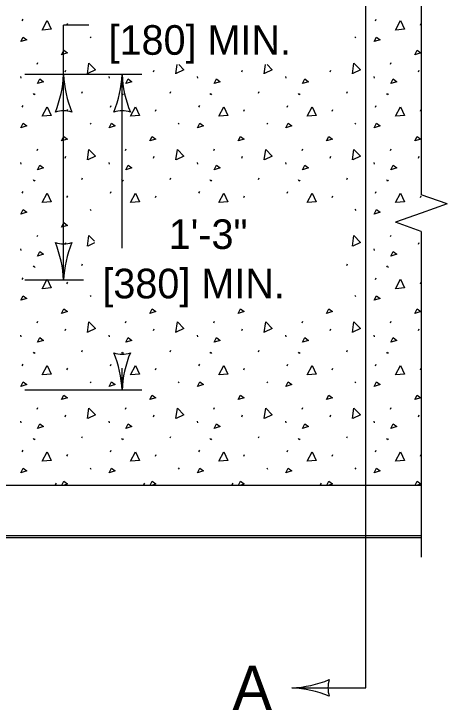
# Model space of a CAD drawing. Extents: x 49991.4 to 50021, y 49987.6 to 50011.4.
# Drawn here: x 50006.829 to 50007.707, y 49990.35 to 49991.76 of the extents above; entities that cross this region are included whole.
import ezdxf

# ---------------------------------------------------------------- set-up
doc = ezdxf.new("R2010")
doc.units = 0
for name, color, linetype in [('Level 1', 7, 'Continuous'), ('Level 2', 7, 'Continuous'), ('Level 3', 7, 'Continuous'), ('Level 6', 7, 'Continuous')]:
    doc.layers.add(name, color=color, linetype=linetype)

msp = doc.modelspace()

# ---------------------------------------------------------------- linework, layer by layer
at = {"layer": 'Level 1'}
for p, q in [((50006.8458, 49991.7465), (50006.8473, 49991.7499)), ((50007.5624, 49991.7465), (50007.5639, 49991.7499)), ((50006.9365, 49991.738), (50006.938, 49991.7413)), ((50007.6532, 49991.738), (50007.6547, 49991.7413)), ((50006.8432, 49991.7044), (50006.8476, 49991.7137)), ((50006.8551, 49991.7081), (50006.8432, 49991.7044)), ((50006.8476, 49991.7137), (50006.8551, 49991.7081)), ((50006.9832, 49991.7141), (50006.9847, 49991.7118)), ((50007.5206, 49991.7141), (50007.5221, 49991.7118)), ((50007.5598, 49991.7044), (50007.5643, 49991.7137)), ((50007.5717, 49991.7081), (50007.5598, 49991.7044)), ((50007.5643, 49991.7137), (50007.5717, 49991.7081)), ((50006.8761, 49991.6585), (50006.8776, 49991.6619)), ((50007.1573, 49991.6394), (50007.1599, 49991.6577)), ((50007.3365, 49991.6394), (50007.339, 49991.6577)), ((50007.5928, 49991.6585), (50007.5942, 49991.6619)), ((50006.9328, 49991.6432), (50006.9343, 49991.6466)), ((50007.112, 49991.6432), (50007.1135, 49991.6466)), ((50007.2911, 49991.6432), (50007.2926, 49991.6466)), ((50007.4703, 49991.6432), (50007.4718, 49991.6466)), ((50007.6494, 49991.6432), (50007.6509, 49991.6466)), ((50006.8423, 49991.6339), (50006.8427, 49991.6305)), ((50007.0215, 49991.6339), (50007.0219, 49991.6305)), ((50007.2006, 49991.6339), (50007.201, 49991.6305)), ((50007.3798, 49991.6339), (50007.3802, 49991.6305)), ((50007.559, 49991.6339), (50007.5593, 49991.6305)), ((50006.8678, 49991.5995), (50006.8693, 49991.5972)), ((50006.8698, 49991.5986), (50006.8713, 49991.5964)), ((50006.9668, 49991.6), (50006.9682, 49991.6033)), ((50007.0469, 49991.5995), (50007.0484, 49991.5972)), ((50007.0489, 49991.5986), (50007.0504, 49991.5964)), ((50007.1459, 49991.6), (50007.1474, 49991.6033)), ((50007.2261, 49991.5995), (50007.2276, 49991.5972)), ((50007.2281, 49991.5986), (50007.2296, 49991.5964)), ((50007.3251, 49991.6), (50007.3266, 49991.6033)), ((50007.4053, 49991.5995), (50007.4068, 49991.5972)), ((50007.4073, 49991.5986), (50007.4087, 49991.5964)), ((50007.5042, 49991.6), (50007.5057, 49991.6033)), ((50007.5844, 49991.5995), (50007.5859, 49991.5972)), ((50007.5864, 49991.5986), (50007.5879, 49991.5964)), ((50006.8458, 49991.5718), (50006.8473, 49991.5752)), ((50006.9365, 49991.5632), (50006.938, 49991.5666)), ((50007.0249, 49991.5718), (50007.0264, 49991.5752)), ((50007.1157, 49991.5632), (50007.1172, 49991.5666)), ((50007.2041, 49991.5718), (50007.2056, 49991.5752)), ((50007.2949, 49991.5632), (50007.2963, 49991.5666)), ((50007.3833, 49991.5718), (50007.3847, 49991.5752)), ((50007.474, 49991.5632), (50007.4755, 49991.5666)), ((50007.5624, 49991.5718), (50007.5639, 49991.5752)), ((50007.6532, 49991.5632), (50007.6547, 49991.5666)), ((50006.8432, 49991.5297), (50006.8476, 49991.539)), ((50006.8476, 49991.539), (50006.8551, 49991.5334)), ((50006.9832, 49991.5394), (50006.9847, 49991.5371)), ((50007.0223, 49991.5297), (50007.0268, 49991.539)), ((50007.0268, 49991.539), (50007.0343, 49991.5334)), ((50007.1623, 49991.5394), (50007.1638, 49991.5371)), ((50007.2015, 49991.5297), (50007.206, 49991.539)), ((50007.206, 49991.539), (50007.2134, 49991.5334)), ((50007.3415, 49991.5394), (50007.343, 49991.5371)), ((50007.3806, 49991.5297), (50007.3851, 49991.539)), ((50007.3851, 49991.539), (50007.3926, 49991.5334)), ((50007.5206, 49991.5394), (50007.5221, 49991.5371)), ((50007.5598, 49991.5297), (50007.5643, 49991.539)), ((50007.5643, 49991.539), (50007.5717, 49991.5334)), ((50006.8551, 49991.5334), (50006.8432, 49991.5297)), ((50007.0343, 49991.5334), (50007.0223, 49991.5297)), ((50007.2134, 49991.5334), (50007.2015, 49991.5297)), ((50007.3926, 49991.5334), (50007.3806, 49991.5297)), ((50007.5717, 49991.5334), (50007.5598, 49991.5297)), ((50006.8761, 49991.4838), (50006.8776, 49991.4871)), ((50007.0553, 49991.4838), (50007.0568, 49991.4871)), ((50007.2344, 49991.4838), (50007.2359, 49991.4871)), ((50007.4136, 49991.4838), (50007.4151, 49991.4871)), ((50007.5928, 49991.4838), (50007.5942, 49991.4871)), ((50006.9328, 49991.4685), (50006.9343, 49991.4719)), ((50007.112, 49991.4685), (50007.1135, 49991.4719)), ((50007.2911, 49991.4685), (50007.2926, 49991.4719)), ((50007.4703, 49991.4685), (50007.4718, 49991.4719)), ((50007.6494, 49991.4685), (50007.6509, 49991.4719)), ((50006.8423, 49991.4591), (50006.8427, 49991.4558)), ((50007.0215, 49991.4591), (50007.0219, 49991.4558)), ((50007.2006, 49991.4591), (50007.201, 49991.4558)), ((50007.3798, 49991.4591), (50007.3802, 49991.4558)), ((50007.559, 49991.4591), (50007.5593, 49991.4558)), ((50006.9668, 49991.4252), (50006.9682, 49991.4286)), ((50007.1459, 49991.4252), (50007.1474, 49991.4286)), ((50007.3251, 49991.4252), (50007.3266, 49991.4286)), ((50007.5042, 49991.4252), (50007.5057, 49991.4286)), ((50006.8678, 49991.4247), (50006.8693, 49991.4225)), ((50006.8698, 49991.4239), (50006.8713, 49991.4216)), ((50007.0469, 49991.4247), (50007.0484, 49991.4225)), ((50007.0489, 49991.4239), (50007.0504, 49991.4216)), ((50007.2261, 49991.4247), (50007.2276, 49991.4225)), ((50007.2281, 49991.4239), (50007.2296, 49991.4216)), ((50007.4053, 49991.4247), (50007.4068, 49991.4225)), ((50007.4073, 49991.4239), (50007.4087, 49991.4216)), ((50007.5844, 49991.4247), (50007.5859, 49991.4225)), ((50007.5864, 49991.4239), (50007.5879, 49991.4216)), ((50006.8458, 49991.3971), (50006.8473, 49991.4004)), ((50007.0249, 49991.3971), (50007.0264, 49991.4004)), ((50007.2041, 49991.3971), (50007.2056, 49991.4004)), ((50007.3833, 49991.3971), (50007.3847, 49991.4004)), ((50007.5624, 49991.3971), (50007.5639, 49991.4004)), ((50006.9365, 49991.3885), (50006.938, 49991.3919)), ((50007.1157, 49991.3885), (50007.1172, 49991.3919)), ((50007.2949, 49991.3885), (50007.2963, 49991.3919)), ((50007.474, 49991.3885), (50007.4755, 49991.3919)), ((50007.6532, 49991.3885), (50007.6547, 49991.3919)), ((50006.8432, 49991.3549), (50006.8476, 49991.3643)), ((50006.8551, 49991.3587), (50006.8432, 49991.3549)), ((50006.8476, 49991.3643), (50006.8551, 49991.3587)), ((50006.9832, 49991.3646), (50006.9847, 49991.3624)), ((50007.5206, 49991.3646), (50007.5221, 49991.3624)), ((50007.5598, 49991.3549), (50007.5643, 49991.3643)), ((50007.5717, 49991.3587), (50007.5598, 49991.3549)), ((50007.5643, 49991.3643), (50007.5717, 49991.3587)), ((50006.8761, 49991.3091), (50006.8776, 49991.3124)), ((50007.5928, 49991.3091), (50007.5942, 49991.3124)), ((50006.8423, 49991.2844), (50006.8427, 49991.2811)), ((50006.9328, 49991.2938), (50006.9343, 49991.2971)), ((50006.9924, 49991.2965), (50006.9785, 49991.29)), ((50007.559, 49991.2844), (50007.5593, 49991.2811)), ((50007.6494, 49991.2938), (50007.6509, 49991.2971)), ((50006.8678, 49991.25), (50006.8693, 49991.2478)), ((50006.8698, 49991.2492), (50006.8713, 49991.2469)), ((50006.9668, 49991.2505), (50006.9682, 49991.2539)), ((50007.5042, 49991.2505), (50007.5057, 49991.2539)), ((50007.5844, 49991.25), (50007.5859, 49991.2478)), ((50007.5864, 49991.2492), (50007.5879, 49991.2469)), ((50006.8458, 49991.2224), (50006.8473, 49991.2257)), ((50006.9365, 49991.2138), (50006.938, 49991.2171)), ((50007.5624, 49991.2224), (50007.5639, 49991.2257)), ((50007.6532, 49991.2138), (50007.6547, 49991.2171)), ((50006.8432, 49991.1802), (50006.8476, 49991.1895)), ((50006.8476, 49991.1895), (50006.8551, 49991.184)), ((50006.9832, 49991.1899), (50006.9847, 49991.1877)), ((50007.5206, 49991.1899), (50007.5221, 49991.1877)), ((50007.5598, 49991.1802), (50007.5643, 49991.1895)), ((50007.5643, 49991.1895), (50007.5717, 49991.184)), ((50006.8551, 49991.184), (50006.8432, 49991.1802)), ((50007.5717, 49991.184), (50007.5598, 49991.1802)), ((50006.8761, 49991.1343), (50006.8776, 49991.1377)), ((50007.0553, 49991.1343), (50007.0568, 49991.1377)), ((50007.2344, 49991.1343), (50007.2359, 49991.1377)), ((50007.4136, 49991.1343), (50007.4151, 49991.1377)), ((50007.5928, 49991.1343), (50007.5942, 49991.1377)), ((50006.9328, 49991.1191), (50006.9343, 49991.1224)), ((50007.112, 49991.1191), (50007.1135, 49991.1224)), ((50007.2911, 49991.1191), (50007.2926, 49991.1224)), ((50007.4703, 49991.1191), (50007.4718, 49991.1224)), ((50007.6494, 49991.1191), (50007.6509, 49991.1224)), ((50006.8423, 49991.1097), (50006.8427, 49991.1063)), ((50007.0215, 49991.1097), (50007.0219, 49991.1063)), ((50007.2006, 49991.1097), (50007.201, 49991.1063)), ((50007.3798, 49991.1097), (50007.3802, 49991.1063)), ((50007.559, 49991.1097), (50007.5593, 49991.1063)), ((50006.8678, 49991.0753), (50006.8693, 49991.0731)), ((50006.8698, 49991.0744), (50006.8713, 49991.0722)), ((50006.9668, 49991.0758), (50006.9682, 49991.0792)), ((50007.0469, 49991.0753), (50007.0484, 49991.0731)), ((50007.0489, 49991.0744), (50007.0504, 49991.0722)), ((50007.1459, 49991.0758), (50007.1474, 49991.0792)), ((50007.2261, 49991.0753), (50007.2276, 49991.0731)), ((50007.2281, 49991.0744), (50007.2296, 49991.0722)), ((50007.3251, 49991.0758), (50007.3266, 49991.0792)), ((50007.4053, 49991.0753), (50007.4068, 49991.0731)), ((50007.4073, 49991.0744), (50007.4087, 49991.0722)), ((50007.5042, 49991.0758), (50007.5057, 49991.0792)), ((50007.5844, 49991.0753), (50007.5859, 49991.0731)), ((50007.5864, 49991.0744), (50007.5879, 49991.0722)), ((50006.8458, 49991.0476), (50006.8473, 49991.051)), ((50007.0249, 49991.0476), (50007.0264, 49991.051)), ((50007.2041, 49991.0476), (50007.2056, 49991.051)), ((50007.3833, 49991.0476), (50007.3847, 49991.051)), ((50007.5624, 49991.0476), (50007.5639, 49991.051)), ((50006.9365, 49991.0391), (50006.938, 49991.0424)), ((50007.1157, 49991.0391), (50007.1172, 49991.0424)), ((50007.2949, 49991.0391), (50007.2963, 49991.0424)), ((50007.474, 49991.0391), (50007.4755, 49991.0424)), ((50007.6532, 49991.0391), (50007.6547, 49991.0424)), ((50006.8432, 49991.0055), (50006.8476, 49991.0148)), ((50006.8551, 49991.0092), (50006.8432, 49991.0055)), ((50006.8476, 49991.0148), (50006.8551, 49991.0092)), ((50006.9832, 49991.0152), (50006.9847, 49991.013)), ((50007.0223, 49991.0055), (50007.0268, 49991.0148)), ((50007.0343, 49991.0092), (50007.0223, 49991.0055)), ((50007.0268, 49991.0148), (50007.0343, 49991.0092)), ((50007.1623, 49991.0152), (50007.1638, 49991.013)), ((50007.2015, 49991.0055), (50007.206, 49991.0148)), ((50007.2134, 49991.0092), (50007.2015, 49991.0055)), ((50007.206, 49991.0148), (50007.2134, 49991.0092)), ((50007.3415, 49991.0152), (50007.343, 49991.013)), ((50007.3806, 49991.0055), (50007.3851, 49991.0148)), ((50007.3926, 49991.0092), (50007.3806, 49991.0055)), ((50007.3851, 49991.0148), (50007.3926, 49991.0092)), ((50007.5206, 49991.0152), (50007.5221, 49991.013)), ((50007.5598, 49991.0055), (50007.5643, 49991.0148)), ((50007.5717, 49991.0092), (50007.5598, 49991.0055)), ((50007.5643, 49991.0148), (50007.5717, 49991.0092)), ((50006.8761, 49990.9596), (50006.8776, 49990.963)), ((50007.0553, 49990.9596), (50007.0568, 49990.963)), ((50007.2344, 49990.9596), (50007.2359, 49990.963)), ((50007.4136, 49990.9596), (50007.4151, 49990.963)), ((50007.5928, 49990.9596), (50007.5942, 49990.963)), ((50006.9328, 49990.9443), (50006.9343, 49990.9477)), ((50007.112, 49990.9443), (50007.1135, 49990.9477)), ((50007.2911, 49990.9443), (50007.2926, 49990.9477)), ((50007.4703, 49990.9443), (50007.4718, 49990.9477)), ((50007.6494, 49990.9443), (50007.6509, 49990.9477)), ((50006.8423, 49990.935), (50006.8427, 49990.9316)), ((50007.0215, 49990.935), (50007.0219, 49990.9316)), ((50007.2006, 49990.935), (50007.201, 49990.9316)), ((50007.3798, 49990.935), (50007.3802, 49990.9316)), ((50007.559, 49990.935), (50007.5593, 49990.9316)), ((50006.9668, 49990.9011), (50006.9682, 49990.9044)), ((50007.1459, 49990.9011), (50007.1474, 49990.9044)), ((50007.3251, 49990.9011), (50007.3266, 49990.9044)), ((50007.5042, 49990.9011), (50007.5057, 49990.9044)), ((50006.8678, 49990.9006), (50006.8693, 49990.8983)), ((50006.8698, 49990.8997), (50006.8713, 49990.8975)), ((50007.0469, 49990.9006), (50007.0484, 49990.8983)), ((50007.0489, 49990.8997), (50007.0504, 49990.8975)), ((50007.2261, 49990.9006), (50007.2276, 49990.8983)), ((50007.2281, 49990.8997), (50007.2296, 49990.8975)), ((50007.4053, 49990.9006), (50007.4068, 49990.8983)), ((50007.4073, 49990.8997), (50007.4087, 49990.8975)), ((50007.5844, 49990.9006), (50007.5859, 49990.8983)), ((50007.5864, 49990.8997), (50007.5879, 49990.8975)), ((50006.8458, 49990.8729), (50006.8473, 49990.8763)), ((50007.0249, 49990.8729), (50007.0264, 49990.8763)), ((50007.2041, 49990.8729), (50007.2056, 49990.8763)), ((50007.3833, 49990.8729), (50007.3847, 49990.8763)), ((50007.5624, 49990.8729), (50007.5639, 49990.8763)), ((50006.9365, 49990.8643), (50006.938, 49990.8677)), ((50007.1157, 49990.8643), (50007.1172, 49990.8677)), ((50007.2949, 49990.8643), (50007.2963, 49990.8677)), ((50007.474, 49990.8643), (50007.4755, 49990.8677)), ((50007.6532, 49990.8643), (50007.6547, 49990.8677)), ((50006.8432, 49990.8308), (50006.8476, 49990.8401)), ((50006.8551, 49990.8345), (50006.8432, 49990.8308)), ((50006.8476, 49990.8401), (50006.8551, 49990.8345)), ((50006.9832, 49990.8405), (50006.9847, 49990.8382)), ((50007.0223, 49990.8308), (50007.0268, 49990.8401)), ((50007.0343, 49990.8345), (50007.0223, 49990.8308)), ((50007.0268, 49990.8401), (50007.0343, 49990.8345)), ((50007.1623, 49990.8405), (50007.1638, 49990.8382)), ((50007.2015, 49990.8308), (50007.206, 49990.8401)), ((50007.2134, 49990.8345), (50007.2015, 49990.8308)), ((50007.206, 49990.8401), (50007.2134, 49990.8345)), ((50007.3415, 49990.8405), (50007.343, 49990.8382)), ((50007.3806, 49990.8308), (50007.3851, 49990.8401)), ((50007.3926, 49990.8345), (50007.3806, 49990.8308)), ((50007.3851, 49990.8401), (50007.3926, 49990.8345)), ((50007.5206, 49990.8405), (50007.5221, 49990.8382)), ((50007.5598, 49990.8308), (50007.5643, 49990.8401)), ((50007.5717, 49990.8345), (50007.5598, 49990.8308)), ((50007.5643, 49990.8401), (50007.5717, 49990.8345)), ((50005.5272, 49990.8057), (50007.455, 49990.8057)), ((50006.9134, 49990.8063), (50006.9149, 49990.8097)), ((50007.0926, 49990.8063), (50007.0941, 49990.8097)), ((50007.2717, 49990.8063), (50007.2732, 49990.8097)), ((50007.4509, 49990.8063), (50007.4524, 49990.8097)), ((50007.455, 49990.8057), (50007.655, 49990.8057)), ((50005.3272, 49990.7036), (50007.655, 49990.7036)), ((50005.3272, 49990.6997), (50007.655, 49990.6997))]:
    msp.add_line(p, q, dxfattribs=at)
for points in [[(50006.8862, 49991.7279), (50006.8963, 49991.7469), (50006.9041, 49991.7294), (50006.8866, 49991.7279)], [(50007.6028, 49991.7279), (50007.6129, 49991.7469), (50007.6207, 49991.7294), (50007.6032, 49991.7279)], [(50006.9254, 49991.6777), (50006.9299, 49991.6871), (50006.9374, 49991.6815), (50006.9254, 49991.6777)], [(50007.6421, 49991.6777), (50007.6465, 49991.6871), (50007.654, 49991.6815), (50007.6421, 49991.6777)], [(50006.9782, 49991.6394), (50006.9811, 49991.6607), (50006.9945, 49991.6469), (50006.9785, 49991.6395)], [(50007.1632, 49991.6577), (50007.1737, 49991.6469), (50007.1577, 49991.6395)], [(50007.3424, 49991.6577), (50007.3528, 49991.6469), (50007.3369, 49991.6395)], [(50007.5157, 49991.6394), (50007.5186, 49991.6607), (50007.532, 49991.6469), (50007.516, 49991.6395)], [(50006.8769, 49991.6194), (50006.8813, 49991.6287), (50006.8888, 49991.6231), (50006.8769, 49991.6194)], [(50007.056, 49991.6194), (50007.0605, 49991.6287), (50007.068, 49991.6231), (50007.056, 49991.6194)], [(50007.2352, 49991.6194), (50007.2397, 49991.6287), (50007.2471, 49991.6231), (50007.2352, 49991.6194)], [(50007.4143, 49991.6194), (50007.4188, 49991.6287), (50007.4263, 49991.6231), (50007.4143, 49991.6194)], [(50007.5935, 49991.6194), (50007.598, 49991.6287), (50007.6054, 49991.6231), (50007.5935, 49991.6194)], [(50006.8862, 49991.5532), (50006.8963, 49991.5722), (50006.9041, 49991.5547), (50006.8866, 49991.5532)], [(50007.0653, 49991.5532), (50007.0754, 49991.5722), (50007.0833, 49991.5547), (50007.0657, 49991.5532)], [(50007.2445, 49991.5532), (50007.2546, 49991.5722), (50007.2624, 49991.5547), (50007.2449, 49991.5532)], [(50007.4237, 49991.5532), (50007.4337, 49991.5722), (50007.4416, 49991.5547), (50007.424, 49991.5532)], [(50007.6028, 49991.5532), (50007.6129, 49991.5722), (50007.6207, 49991.5547), (50007.6032, 49991.5532)], [(50006.9254, 49991.503), (50006.9299, 49991.5123), (50006.9374, 49991.5067), (50006.9254, 49991.503)], [(50007.1046, 49991.503), (50007.1091, 49991.5123), (50007.1165, 49991.5067), (50007.1046, 49991.503)], [(50007.2837, 49991.503), (50007.2882, 49991.5123), (50007.2957, 49991.5067), (50007.2837, 49991.503)], [(50007.4629, 49991.503), (50007.4674, 49991.5123), (50007.4748, 49991.5067), (50007.4629, 49991.503)], [(50007.6421, 49991.503), (50007.6465, 49991.5123), (50007.654, 49991.5067), (50007.6421, 49991.503)], [(50006.9782, 49991.4646), (50006.9811, 49991.486), (50006.9945, 49991.4722), (50006.9785, 49991.4648)], [(50007.1573, 49991.4646), (50007.1603, 49991.486), (50007.1737, 49991.4722), (50007.1577, 49991.4648)], [(50007.3365, 49991.4646), (50007.3395, 49991.486), (50007.3528, 49991.4722), (50007.3369, 49991.4648)], [(50007.5157, 49991.4646), (50007.5186, 49991.486), (50007.532, 49991.4722), (50007.516, 49991.4648)], [(50006.8769, 49991.4446), (50006.8813, 49991.454), (50006.8888, 49991.4484), (50006.8769, 49991.4446)], [(50007.056, 49991.4446), (50007.0605, 49991.454), (50007.068, 49991.4484), (50007.056, 49991.4446)], [(50007.2352, 49991.4446), (50007.2397, 49991.454), (50007.2471, 49991.4484), (50007.2352, 49991.4446)], [(50007.4143, 49991.4446), (50007.4188, 49991.454), (50007.4263, 49991.4484), (50007.4143, 49991.4446)], [(50007.5935, 49991.4446), (50007.598, 49991.454), (50007.6054, 49991.4484), (50007.5935, 49991.4446)], [(50006.8862, 49991.3784), (50006.8963, 49991.3975), (50006.9041, 49991.3799), (50006.8866, 49991.3784)], [(50007.0653, 49991.3784), (50007.0754, 49991.3975), (50007.0833, 49991.3799), (50007.0657, 49991.3784)], [(50007.2445, 49991.3784), (50007.2546, 49991.3975), (50007.2624, 49991.3799), (50007.2449, 49991.3784)], [(50007.4237, 49991.3784), (50007.4337, 49991.3975), (50007.4416, 49991.3799), (50007.424, 49991.3784)], [(50007.6028, 49991.3784), (50007.6129, 49991.3975), (50007.6207, 49991.3799), (50007.6032, 49991.3784)], [(50006.9254, 49991.3283), (50006.9299, 49991.3376), (50006.9374, 49991.332), (50006.9254, 49991.3283)], [(50006.9782, 49991.2899), (50006.9811, 49991.3112), (50006.9924, 49991.2997)], [(50007.5157, 49991.2899), (50007.5186, 49991.3112), (50007.532, 49991.2974), (50007.516, 49991.29)], [(50006.8769, 49991.2699), (50006.8813, 49991.2792), (50006.8888, 49991.2736), (50006.8769, 49991.2699)], [(50007.5935, 49991.2699), (50007.598, 49991.2792), (50007.6054, 49991.2736), (50007.5935, 49991.2699)], [(50006.8862, 49991.2037), (50006.8963, 49991.2227), (50006.9041, 49991.2052), (50006.8866, 49991.2037)], [(50007.6028, 49991.2037), (50007.6129, 49991.2227), (50007.6207, 49991.2052), (50007.6032, 49991.2037)], [(50006.9254, 49991.1536), (50006.9299, 49991.1629), (50006.9374, 49991.1573), (50006.9254, 49991.1536)], [(50007.1046, 49991.1536), (50007.1091, 49991.1629), (50007.1165, 49991.1573), (50007.1046, 49991.1536)], [(50007.2837, 49991.1536), (50007.2882, 49991.1629), (50007.2957, 49991.1573), (50007.2837, 49991.1536)], [(50007.4629, 49991.1536), (50007.4674, 49991.1629), (50007.4748, 49991.1573), (50007.4629, 49991.1536)], [(50007.6421, 49991.1536), (50007.6465, 49991.1629), (50007.654, 49991.1573), (50007.6421, 49991.1536)], [(50006.9782, 49991.1152), (50006.9811, 49991.1365), (50006.9945, 49991.1227), (50006.9785, 49991.1153)], [(50007.1573, 49991.1152), (50007.1603, 49991.1365), (50007.1737, 49991.1227), (50007.1577, 49991.1153)], [(50007.3365, 49991.1152), (50007.3395, 49991.1365), (50007.3528, 49991.1227), (50007.3369, 49991.1153)], [(50007.5157, 49991.1152), (50007.5186, 49991.1365), (50007.532, 49991.1227), (50007.516, 49991.1153)], [(50006.8769, 49991.0952), (50006.8813, 49991.1045), (50006.8888, 49991.0989), (50006.8769, 49991.0952)], [(50007.056, 49991.0952), (50007.0605, 49991.1045), (50007.068, 49991.0989), (50007.056, 49991.0952)], [(50007.2352, 49991.0952), (50007.2397, 49991.1045), (50007.2471, 49991.0989), (50007.2352, 49991.0952)], [(50007.4143, 49991.0952), (50007.4188, 49991.1045), (50007.4263, 49991.0989), (50007.4143, 49991.0952)], [(50007.5935, 49991.0952), (50007.598, 49991.1045), (50007.6054, 49991.0989), (50007.5935, 49991.0952)], [(50006.8862, 49991.029), (50006.8963, 49991.048), (50006.9041, 49991.0305), (50006.8866, 49991.029)], [(50007.0653, 49991.029), (50007.0754, 49991.048), (50007.0833, 49991.0305), (50007.0657, 49991.029)], [(50007.2445, 49991.029), (50007.2546, 49991.048), (50007.2624, 49991.0305), (50007.2449, 49991.029)], [(50007.4237, 49991.029), (50007.4337, 49991.048), (50007.4416, 49991.0305), (50007.424, 49991.029)], [(50007.6028, 49991.029), (50007.6129, 49991.048), (50007.6207, 49991.0305), (50007.6032, 49991.029)], [(50006.9254, 49990.9788), (50006.9299, 49990.9882), (50006.9374, 49990.9826), (50006.9254, 49990.9788)], [(50007.1046, 49990.9788), (50007.1091, 49990.9882), (50007.1165, 49990.9826), (50007.1046, 49990.9788)], [(50007.2837, 49990.9788), (50007.2882, 49990.9882), (50007.2957, 49990.9826), (50007.2837, 49990.9788)], [(50007.4629, 49990.9788), (50007.4674, 49990.9882), (50007.4748, 49990.9826), (50007.4629, 49990.9788)], [(50007.6421, 49990.9788), (50007.6465, 49990.9882), (50007.654, 49990.9826), (50007.6421, 49990.9788)], [(50006.9782, 49990.9405), (50006.9811, 49990.9618), (50006.9945, 49990.948), (50006.9785, 49990.9406)], [(50007.1573, 49990.9405), (50007.1603, 49990.9618), (50007.1737, 49990.948), (50007.1577, 49990.9406)], [(50007.3365, 49990.9405), (50007.3395, 49990.9618), (50007.3528, 49990.948), (50007.3369, 49990.9406)], [(50007.5157, 49990.9405), (50007.5186, 49990.9618), (50007.532, 49990.948), (50007.516, 49990.9406)], [(50006.8769, 49990.9205), (50006.8813, 49990.9298), (50006.8888, 49990.9242), (50006.8769, 49990.9205)], [(50007.056, 49990.9205), (50007.0605, 49990.9298), (50007.068, 49990.9242), (50007.056, 49990.9205)], [(50007.2352, 49990.9205), (50007.2397, 49990.9298), (50007.2471, 49990.9242), (50007.2352, 49990.9205)], [(50007.4143, 49990.9205), (50007.4188, 49990.9298), (50007.4263, 49990.9242), (50007.4143, 49990.9205)], [(50007.5935, 49990.9205), (50007.598, 49990.9298), (50007.6054, 49990.9242), (50007.5935, 49990.9205)], [(50006.8862, 49990.8543), (50006.8963, 49990.8733), (50006.9041, 49990.8558), (50006.8866, 49990.8543)], [(50007.0653, 49990.8543), (50007.0754, 49990.8733), (50007.0833, 49990.8558), (50007.0657, 49990.8543)], [(50007.2445, 49990.8543), (50007.2546, 49990.8733), (50007.2624, 49990.8558), (50007.2449, 49990.8543)], [(50007.4237, 49990.8543), (50007.4337, 49990.8733), (50007.4416, 49990.8558), (50007.424, 49990.8543)], [(50007.6028, 49990.8543), (50007.6129, 49990.8733), (50007.6207, 49990.8558), (50007.6032, 49990.8543)], [(50006.9262, 49990.8057), (50006.9299, 49990.8134), (50006.9374, 49990.8079), (50006.9305, 49990.8057)], [(50007.1053, 49990.8057), (50007.1091, 49990.8134), (50007.1165, 49990.8079), (50007.1096, 49990.8057)], [(50007.2845, 49990.8057), (50007.2882, 49990.8134), (50007.2957, 49990.8079), (50007.2888, 49990.8057)], [(50007.4637, 49990.8057), (50007.4674, 49990.8134), (50007.4748, 49990.8079), (50007.4679, 49990.8057)], [(50007.6428, 49990.8057), (50007.6465, 49990.8134), (50007.654, 49990.8079), (50007.6471, 49990.8057)]]:
    msp.add_lwpolyline(points, dxfattribs=at)
at = {"layer": 'Level 3'}
for p, q in [((50007.5423, 49990.3947), (50007.5423, 49992.6269)), ((50006.9297, 49991.6377), (50006.9297, 49991.7377)), ((50006.9808, 49991.7377), (50006.9297, 49991.7377)), ((50007.0883, 49991.6377), (50006.8511, 49991.6377)), ((50006.9297, 49991.2209), (50006.9297, 49991.6377)), ((50007.0483, 49991.2861), (50007.0483, 49991.6377)), ((50006.9697, 49991.2209), (50006.8511, 49991.2209)), ((50007.0483, 49990.9977), (50007.0483, 49991.0426)), ((50007.0883, 49990.9977), (50006.8511, 49990.9977)), ((50007.3923, 49990.3947), (50007.5423, 49990.3947))]:
    msp.add_line(p, q, dxfattribs=at)
for centre, radius, start, end in [((50006.697, 49991.6492), 0.233, 337.9228, 357.1727), ((50007.1518, 49991.6468), 0.2223, 182.3605, 202.544), ((50006.8156, 49991.6492), 0.233, 337.9228, 357.1727), ((50007.2704, 49991.6468), 0.2223, 182.3605, 202.544), ((50006.9297, 49991.5095), 0.0548, 72.1388, 107.8612), ((50007.0483, 49991.5095), 0.0548, 72.1388, 107.8612), ((50006.9297, 49991.3491), 0.0548, 252.1388, 287.8612), ((50006.697, 49991.2094), 0.233, 2.8273, 22.0772), ((50007.1518, 49991.2117), 0.2223, 157.456, 177.6395), ((50007.0483, 49991.1259), 0.0548, 252.1388, 287.8612), ((50006.8156, 49990.9862), 0.233, 2.8273, 22.0772), ((50007.2704, 49990.9885), 0.2223, 157.456, 177.6395), ((50007.3832, 49990.6168), 0.2223, 272.3605, 292.544), ((50007.5206, 49990.3947), 0.0548, 162.1388, 197.8612), ((50007.3808, 49990.162), 0.233, 67.9228, 87.1727)]:
    msp.add_arc(centre, radius, start, end, dxfattribs=at)
at = {"layer": 'Level 6'}
for p, q in [((50007.655, 49992.3669), (50007.655, 49991.5129)), ((50007.655, 49991.5129), (50007.655, 49991.394)), ((50007.7074, 49991.3755), (50007.655, 49991.394)), ((50007.7074, 49991.3755), (50007.655, 49991.3569)), ((50007.655, 49991.3569), (50007.6027, 49991.3384)), ((50007.655, 49991.3198), (50007.6027, 49991.3384)), ((50007.655, 49991.3198), (50007.655, 49991.2019)), ((50007.655, 49991.2019), (50007.655, 49990.6597))]:
    msp.add_line(p, q, dxfattribs=at)

# ---------------------------------------------------------------- texts
at = {"layer": 'Level 2'}
for s, height, p in [('[180] MIN.', 0.06, (50007.0208, 49991.6777)), ('1\'-3" ', 0.06, (50007.1429, 49991.2841)), ('[380] MIN.', 0.06, (50007.0082, 49991.1841)), ('A', 0.09, (50007.2721, 49990.3497))]:
    msp.add_text(s, height=height, dxfattribs=at).set_placement(p)

doc.saveas('drawing.dxf')
